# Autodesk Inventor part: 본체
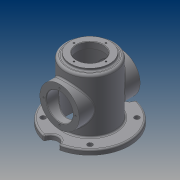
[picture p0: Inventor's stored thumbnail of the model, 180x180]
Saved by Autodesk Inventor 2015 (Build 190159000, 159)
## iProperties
Created: 2018-04
Part Number: 본체
Material: 일반
Document SubType Name: Modeling
Designer: user
Density: 1 g/cm^3
Appearance: 기본값
Author: user
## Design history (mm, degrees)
sketch "스케치1"
  geometry: L1 (0, 65)-(0, -60); L2 (-40, 65)-(-40, 60); L3 (-40, 60)-(-45, 60); L4 (-50, 55)-(-50, -47); L5 (-53, -50)-(-80, -50); L6 (-80, -50)-(-80, -60); L7 (-80, -60)-(-45, -60); L8 (-40, 65)-(-27, 65); L9 (-27, 65)-(-27, 52); L10 (-27, 52)-(-42, 52); L11 (-45, 49)-(-45, -60); A1 r 5 centre (-45, 55) between (-45, 60) and (-50, 55); A2 r 3 centre (-42, 49) between (-42, 52) and (-45, 49); A3 r 3 centre (-53, -47) between (-53, -50) and (-50, -47); 5 further points
  constraints: 22 end point, 7 perpendicular, 6 point on circle, 6 point on line, 6 tangent, 3 centre point, 2 horizontal alignment, 2 vertical, 1 horizontal, 1 midpoint, 1 vertical alignment
  dimensions: "d0" = 125 distance of L1.start L1.end; "d1" = 60 distance of point (0, 0) L1.end; "d2" = 54 diameter of L9 L1; "d3" = 80 diameter of L2 L1; "d4" = 10 distance between parallel lines of L7 L5; "d5" = 160 diameter of L6 L1; "d6" = 13 distance between parallel lines of L8 L10; "d7" = 110 distance between parallel lines of L5 L3; "d8" = 100 diameter of L4 L1; "d9" = 90 diameter of L11 L1; "d14" = 5 radius of A1; "d15" = 3 radius of A2; "d16" = 3 radius of A3
revolve "회전1" sketch "스케치1" stored, may be unused: angle "d10" = 90 deg
sketch "스케치2"
  geometry: C1 r 45 at (0, 0) reference; C2 r 80 at (0, 0) reference; C3 r 50 at (0, 0)
  constraints: 1 centre point, 1 coincident
  dimensions: "d11" = 100 diameter of C3
extrude "돌출1" join sketch "스케치2" distance "d12" = 8; taper "d13" = 0 deg
node "작업 평면1"
sketch "스케치3"
  geometry: C1 r 40 at (0, 0); C2 r 27 at (0, 0); 2 further points
  constraints: 2 centre point, 2 coincident, 1 vertical alignment
  dimensions: "d18" = 80 diameter of C1; "d19" = 54 diameter of C2; "d24" = 32.5 distance of point (0, 0) point (0, 32.5)
extrude "돌출2" join sketch "스케치3" stored distance "d20" = 8; taper "d21" = 0 deg
extrude "돌출3" cut sketch "스케치3" stored distance "d22" = 8; taper "d23" = 0 deg
hole "구멍1" sketch "스케치3" diameter "d25" = 3.242; stored, may be unused: countersink angle "d29" = 90 deg, drill point angle "d31" = 118 deg; dims "d26" = 8, "d27" = 4, "d28" = 2, "d30" = 10
sketch "스케치4"
  geometry: C1 r 40 at (0, 0) reference; 1 further point
  constraints: 1 vertical alignment
  dimensions: "d35" = 32.5 distance of C1.centre point (0, 32.5)
hole "구멍2" sketch "스케치4" at (0, 32.5) diameter "d36" = 3.242; stored, may be unused: countersink angle "d40" = 90 deg, drill point angle "d42" = 118 deg; dims "d37" = 8, "d38" = 4, "d39" = 2, "d41" = 10
sketch "스케치5" dims "d48" = 135
  geometry: L1 (0, 0)-(-99.526, 0); L2 (0, 0)-(-47.73, -47.73); C1 r 53 at (0, 0) reference; C2 r 15 at (0, -80); C3 r 15 at (0, 80); C4 r 5 at (-47.73, -47.73); A1 r 80 centre (0, 0) between (0, -80) and (0, 80) reference
  constraints: 4 end point, 3 centre point, 2 coincident, 2 point on circle, 2 vertical alignment, 1 horizontal, 3 other
  dimensions: "d46" = 30 diameter of C2; "d47" = 30 diameter of C3; "d49" = 45 deg angle of L1 L2; "d50" = 10 diameter of C4
extrude "돌출4" cut sketch "스케치5" stored distance "d51" = 8; taper "d52" = 0 deg
extrude "돌출5" cut sketch "스케치5" stored distance "d53" = 8; taper "d54" = 0 deg
fillet "모깎기1" dims "d58" = 3
chamfer "모따기1" distance "d59" = 1; stored, may be unused: second distance "d60" = 2, angle "d61" = 45 deg
fillet "모깎기2" dims "d62" = 3
fillet "모깎기3" dims "d63" = 3
node "솔리드1"
pattern_circular "원형 패턴1" dims angle "d33" = 360 deg
mirror "대칭1"
pattern_circular "원형 패턴2" dims angle "d44" = 360 deg
pattern_circular "원형 패턴3" dims angle "d56" = 360 deg
other parameters: "d17" = 62
